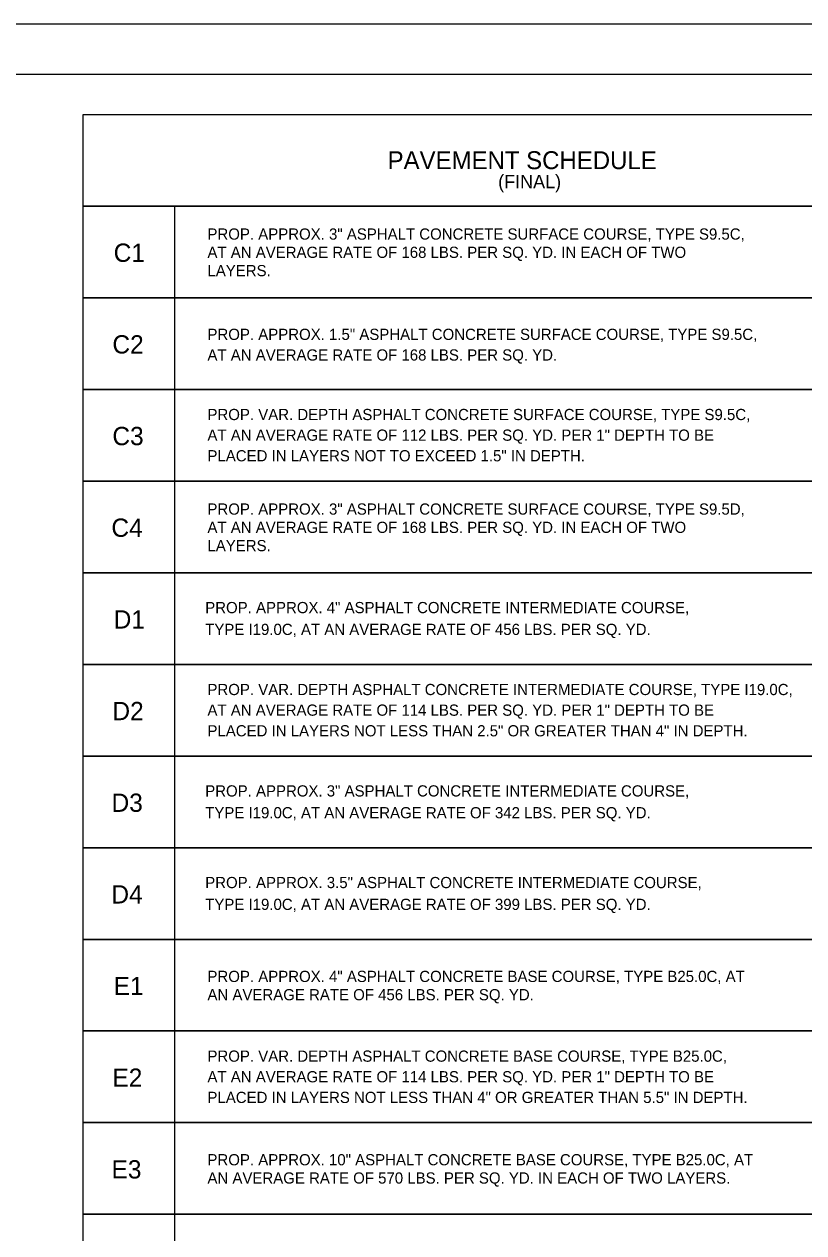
# Model space of a CAD drawing. Extents: x 1553884 to 1554215, y 810431 to 810779.
# Drawn here: x 1554073.1 to 1554125.3, y 810698.5 to 810779.4 of the extents above; entities that cross this region are included whole.
import ezdxf

# ---------------------------------------------------------------- set-up
doc = ezdxf.new("R2010")
doc.units = 0
for name, color, linetype in [('Old_Level_2', 7, 'Continuous'), ('Prop Dimension', 7, 'Continuous'), ('Prop Lane Arrow CELL', 7, 'Continuous'), ('Typical Detail Pavement Repair CELL', 7, 'Continuous')]:
    doc.layers.add(name, color=color, linetype=linetype)

msp = doc.modelspace()

# ---------------------------------------------------------------- linework, layer by layer
at = {"layer": 'Old_Level_2'}
msp.add_line((1554154.325, 810776.052), (1553906.825, 810776.052), dxfattribs=at)
at = {"layer": 'Prop Dimension'}
msp.add_lwpolyline([(1554077.027, 810773.388), (1554137.029, 810773.388), (1554137.029, 810767.252), (1554077.027, 810767.252)], close=True, dxfattribs=at)
for points in [[(1554083.164, 810761.114), (1554077.027, 810761.114), (1554077.027, 810767.252), (1554137.027, 810767.252), (1554137.027, 810761.114), (1554083.164, 810761.114), (1554083.164, 810767.252)], [(1554083.164, 810754.977), (1554077.027, 810754.977), (1554077.027, 810761.114), (1554137.027, 810761.114), (1554137.027, 810754.977), (1554083.164, 810754.977), (1554083.164, 810761.114)], [(1554083.164, 810748.839), (1554077.027, 810748.839), (1554077.027, 810754.977), (1554137.027, 810754.977), (1554137.027, 810748.839), (1554083.164, 810748.839), (1554083.164, 810754.977)], [(1554083.164, 810742.702), (1554077.027, 810742.702), (1554077.027, 810748.839), (1554137.027, 810748.839), (1554137.027, 810742.702), (1554083.164, 810742.702), (1554083.164, 810748.839)], [(1554083.164, 810736.565), (1554077.027, 810736.565), (1554077.027, 810742.702), (1554137.027, 810742.702), (1554137.027, 810736.565), (1554083.164, 810736.565), (1554083.164, 810742.702)], [(1554083.164, 810730.428), (1554077.027, 810730.428), (1554077.027, 810736.565), (1554137.027, 810736.565), (1554137.027, 810730.428), (1554083.164, 810730.428), (1554083.164, 810736.565)], [(1554083.164, 810724.292), (1554077.027, 810724.292), (1554077.027, 810730.428), (1554137.027, 810730.428), (1554137.027, 810724.292), (1554083.164, 810724.292), (1554083.164, 810730.428)], [(1554083.164, 810718.155), (1554077.027, 810718.155), (1554077.027, 810724.292), (1554137.027, 810724.292), (1554137.027, 810718.155), (1554083.164, 810718.155), (1554083.164, 810724.292)], [(1554083.164, 810712.019), (1554077.027, 810712.019), (1554077.027, 810718.155), (1554137.027, 810718.155), (1554137.027, 810712.019), (1554083.164, 810712.019), (1554083.164, 810718.155)], [(1554083.164, 810705.882), (1554077.027, 810705.882), (1554077.027, 810712.019), (1554137.027, 810712.019), (1554137.027, 810705.882), (1554083.164, 810705.882), (1554083.164, 810712.019)], [(1554083.164, 810699.745), (1554077.027, 810699.745), (1554077.027, 810705.882), (1554137.027, 810705.882), (1554137.027, 810699.745), (1554083.164, 810699.745), (1554083.164, 810705.882)], [(1554083.164, 810693.609), (1554077.027, 810693.609), (1554077.027, 810699.745), (1554137.027, 810699.745), (1554137.027, 810693.609), (1554083.164, 810693.609), (1554083.164, 810699.745)]]:
    msp.add_lwpolyline(points, dxfattribs=at)
at = {"layer": 'Prop Lane Arrow CELL'}
msp.add_line((1554156.35, 810779.427), (1553901.353, 810779.427), dxfattribs=at)

# ---------------------------------------------------------------- texts
at = {"layer": 'Prop Dimension'}
for s, height, p in [('PAVEMENT SCHEDULE', 1.2, (1554097.411, 810769.72)), ('PROP. APPROX. 3" ASPHALT CONCRETE SURFACE COURSE, TYPE S9.5C, ', 0.75, (1554085.351, 810765.001)), ('C1', 1.225, (1554079.073, 810763.514)), ('AT AN AVERAGE RATE OF 168 LBS. PER SQ. YD. IN EACH OF TWO ', 0.75, (1554085.351, 810763.778)), ('LAYERS.', 0.75, (1554085.351, 810762.554)), ('C2', 1.225, (1554078.988, 810757.377)), ('PROP. APPROX. 1.5" ASPHALT CONCRETE SURFACE COURSE, TYPE S9.5C,', 0.75, (1554085.351, 810758.286)), ('AT AN AVERAGE RATE OF 168 LBS. PER SQ. YD.', 0.75, (1554085.351, 810756.904)), ('PROP. VAR. DEPTH ASPHALT CONCRETE SURFACE COURSE, TYPE S9.5C,', 0.75, (1554085.351, 810752.919)), ('C3', 1.225, (1554078.987, 810751.239)), ('AT AN AVERAGE RATE OF 112 LBS. PER SQ. YD. PER 1" DEPTH TO BE', 0.75, (1554085.351, 810751.537)), ('PLACED IN LAYERS NOT TO EXCEED 1.5" IN DEPTH.', 0.75, (1554085.351, 810750.156)), ('PROP. APPROX. 3" ASPHALT CONCRETE SURFACE COURSE, TYPE S9.5D, ', 0.75, (1554085.351, 810746.589)), ('C4', 1.225, (1554078.92, 810745.102)), ('AT AN AVERAGE RATE OF 168 LBS. PER SQ. YD. IN EACH OF TWO ', 0.75, (1554085.351, 810745.365)), ('LAYERS.', 0.75, (1554085.351, 810744.142)), ('PROP. APPROX. 4" ASPHALT CONCRETE INTERMEDIATE COURSE,', 0.75, (1554085.201, 810739.992)), ('D1', 1.225, (1554079.073, 810738.964)), ('TYPE I19.0C, AT AN AVERAGE RATE OF 456 LBS. PER SQ. YD.', 0.75, (1554085.201, 810738.532)), ('PROP. VAR. DEPTH ASPHALT CONCRETE INTERMEDIATE COURSE, TYPE I19.0C,', 0.75, (1554085.351, 810734.507)), ('D2', 1.225, (1554078.988, 810732.828)), ('AT AN AVERAGE RATE OF 114 LBS. PER SQ. YD. PER 1" DEPTH TO BE', 0.75, (1554085.351, 810733.126)), ('PLACED IN LAYERS NOT LESS THAN 2.5" OR GREATER THAN 4" IN DEPTH.', 0.75, (1554085.351, 810731.744)), ('D3', 1.225, (1554078.93, 810726.69)), ('PROP. APPROX. 3" ASPHALT CONCRETE INTERMEDIATE COURSE,', 0.75, (1554085.201, 810727.718)), ('TYPE I19.0C, AT AN AVERAGE RATE OF 342 LBS. PER SQ. YD.', 0.75, (1554085.201, 810726.258)), ('PROP. APPROX. 3.5" ASPHALT CONCRETE INTERMEDIATE COURSE,', 0.75, (1554085.201, 810721.582)), ('D4', 1.225, (1554078.92, 810720.554)), ('TYPE I19.0C, AT AN AVERAGE RATE OF 399 LBS. PER SQ. YD.', 0.75, (1554085.201, 810720.122)), ('PROP. APPROX. 4" ASPHALT CONCRETE BASE COURSE, TYPE B25.0C, AT', 0.75, (1554085.351, 810715.299)), ('E1', 1.225, (1554079.073, 810714.418)), ('AN AVERAGE RATE OF 456 LBS. PER SQ. YD.', 0.75, (1554085.351, 810714.075)), ('PROP. VAR. DEPTH ASPHALT CONCRETE BASE COURSE, TYPE B25.0C,', 0.75, (1554085.351, 810709.961)), ('E2', 1.225, (1554078.988, 810708.282)), ('AT AN AVERAGE RATE OF 114 LBS. PER SQ. YD. PER 1" DEPTH TO BE', 0.75, (1554085.351, 810708.58)), ('PLACED IN LAYERS NOT LESS THAN 4" OR GREATER THAN 5.5" IN DEPTH.', 0.75, (1554085.351, 810707.198)), ('PROP. APPROX. 10" ASPHALT CONCRETE BASE COURSE, TYPE B25.0C, AT', 0.75, (1554085.351, 810703.025)), ('E3', 1.225, (1554078.93, 810702.144)), ('AN AVERAGE RATE OF 570 LBS. PER SQ. YD. IN EACH OF TWO LAYERS.', 0.75, (1554085.351, 810701.802))]:
    msp.add_text(s, height=height, dxfattribs=at).set_placement(p)
at = {"layer": 'Typical Detail Pavement Repair CELL'}
msp.add_text('(FINAL)', height=0.9, dxfattribs=at).set_placement((1554104.81, 810768.438))

doc.saveas('drawing.dxf')
